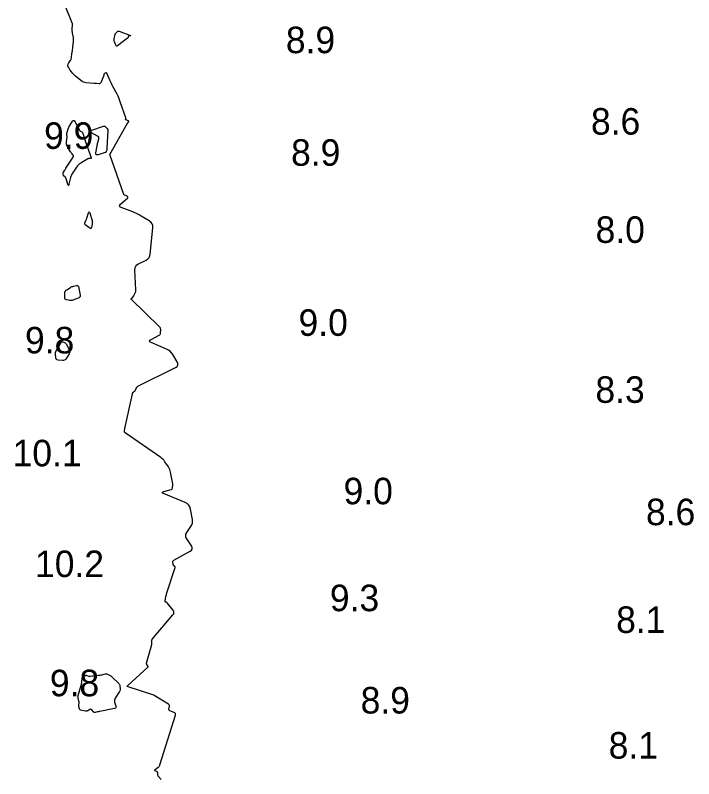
# Model space of a CAD drawing. Extents: x 1023796 to 1112670, y 656573 to 837340.
# Drawn here: x 1100706.3 to 1100834.2, y 688188.2 to 688332.1 of the extents above; entities that cross this region are included whole.
import ezdxf

# ---------------------------------------------------------------- set-up
doc = ezdxf.new("R2010")
doc.units = 0
doc.layers.add('V-CHAN-CONT-10FT', color=7, linetype='Continuous')
doc.layers.add('V-TOPO-SOUN', color=7, linetype='Continuous')

msp = doc.modelspace()

# ---------------------------------------------------------------- linework, layer by layer
at = {"layer": 'V-CHAN-CONT-10FT'}
msp.add_lwpolyline([(1100733.76, 688188.01), (1100733.28, 688188.6), (1100733.24, 688188.67), (1100733.2, 688188.73), (1100733.18, 688188.81), (1100733.17, 688188.88), (1100733.15, 688189.19), (1100733.13, 688189.27), (1100733.11, 688189.33), (1100733.06, 688189.39), (1100733.01, 688189.43), (1100732.67, 688189.65), (1100732.61, 688189.7), (1100732.59, 688189.75), (1100732.61, 688189.81), (1100732.66, 688189.87), (1100733.23, 688190.32), (1100733.34, 688190.42), (1100733.43, 688190.53), (1100733.5, 688190.66), (1100733.55, 688190.8), (1100736.46, 688200.14), (1100736.49, 688200.3), (1100736.46, 688200.44), (1100736.37, 688200.55), (1100736.22, 688200.63), (1100735.44, 688200.93), (1100735.33, 688200.99), (1100735.26, 688201.07), (1100735.23, 688201.17), (1100735.24, 688201.29), (1100735.34, 688201.83), (1100735.34, 688201.96), (1100735.31, 688202.07), (1100735.25, 688202.16), (1100735.15, 688202.24), (1100732.47, 688203.82), (1100732.46, 688203.83), (1100732.45, 688203.84), (1100732.45, 688203.85), (1100732.45, 688203.86), (1100732.44, 688203.91), (1100732.44, 688203.92), (1100732.43, 688203.93), (1100732.42, 688203.94), (1100732.41, 688203.94), (1100727.39, 688205.52), (1100727.37, 688205.53), (1100727.36, 688205.54), (1100727.36, 688205.55), (1100727.37, 688205.57), (1100727.44, 688205.65), (1100727.45, 688205.67), (1100727.47, 688205.68), (1100727.49, 688205.7), (1100727.51, 688205.72), (1100731.25, 688209.16), (1100731.3, 688209.22), (1100731.32, 688209.28), (1100731.31, 688209.34), (1100731.27, 688209.4), (1100731.09, 688209.67), (1100731.05, 688209.74), (1100731.03, 688209.81), (1100731.02, 688209.88), (1100731.04, 688209.96), (1100732.01, 688213.47), (1100732.03, 688213.56), (1100732.05, 688213.65), (1100732.05, 688213.75), (1100732.05, 688213.84), (1100732.04, 688214.22), (1100732.05, 688214.31), (1100732.07, 688214.39), (1100732.11, 688214.47), (1100732.16, 688214.55), (1100735.99, 688219.04), (1100736.14, 688219.27), (1100736.19, 688219.5), (1100736.15, 688219.73), (1100736.01, 688219.97), (1100734.93, 688221.31), (1100734.89, 688221.34), (1100734.86, 688221.37), (1100734.82, 688221.39), (1100734.78, 688221.41), (1100734.6, 688221.47), (1100734.56, 688221.49), (1100734.53, 688221.52), (1100734.52, 688221.55), (1100734.52, 688221.6), (1100734.68, 688222.53), (1100734.72, 688222.69), (1100734.76, 688222.86), (1100734.8, 688223.03), (1100734.85, 688223.19), (1100736.4, 688227.95), (1100736.41, 688228.02), (1100736.41, 688228.08), (1100736.38, 688228.13), (1100736.34, 688228.18), (1100736.13, 688228.37), (1100736.08, 688228.42), (1100736.05, 688228.48), (1100736.03, 688228.54), (1100736.02, 688228.61), (1100735.99, 688229.08), (1100736, 688229.17), (1100736.03, 688229.26), (1100736.09, 688229.32), (1100736.16, 688229.38), (1100739.23, 688231.03), (1100739.5, 688231.23), (1100739.63, 688231.46), (1100739.62, 688231.73), (1100739.48, 688232.04), (1100738.6, 688233.38), (1100738.45, 688233.67), (1100738.41, 688233.97), (1100738.46, 688234.26), (1100738.6, 688234.56), (1100739.39, 688235.73), (1100739.56, 688236.03), (1100739.66, 688236.34), (1100739.69, 688236.67), (1100739.67, 688237.01), (1100739.32, 688238.98), (1100739.2, 688239.39), (1100739, 688239.74), (1100738.71, 688240.01), (1100738.33, 688240.22), (1100734.24, 688241.9), (1100734.04, 688242.01), (1100733.98, 688242.11), (1100734.05, 688242.2), (1100734.26, 688242.28), (1100735.68, 688242.69), (1100735.79, 688242.74), (1100735.87, 688242.81), (1100735.92, 688242.9), (1100735.94, 688243.02), (1100735.97, 688243.53), (1100735.97, 688243.66), (1100735.96, 688243.79), (1100735.95, 688243.92), (1100735.93, 688244.04), (1100735.57, 688245.92), (1100735.5, 688246.19), (1100735.41, 688246.46), (1100735.29, 688246.71), (1100735.14, 688246.96), (1100734.49, 688247.91), (1100734.32, 688248.14), (1100734.13, 688248.35), (1100733.92, 688248.54), (1100733.69, 688248.71), (1100726.98, 688253.37), (1100726.93, 688253.42), (1100726.89, 688253.47), (1100726.87, 688253.53), (1100726.87, 688253.6), (1100726.89, 688253.88), (1100726.9, 688253.95), (1100726.91, 688254.02), (1100726.92, 688254.09), (1100726.93, 688254.15), (1100728.35, 688260.73), (1100728.38, 688260.82), (1100728.41, 688260.9), (1100728.46, 688260.97), (1100728.53, 688261.03), (1100728.8, 688261.28), (1100728.86, 688261.34), (1100728.92, 688261.41), (1100728.97, 688261.49), (1100729.01, 688261.57), (1100729.17, 688261.9), (1100729.21, 688261.98), (1100729.27, 688262.05), (1100729.33, 688262.1), (1100729.41, 688262.15), (1100736.51, 688265.69), (1100736.8, 688265.89), (1100736.95, 688266.14), (1100736.95, 688266.42), (1100736.82, 688266.75), (1100735.98, 688268.14), (1100735.75, 688268.46), (1100735.48, 688268.74), (1100735.17, 688268.97), (1100734.81, 688269.15), (1100731.9, 688270.39), (1100731.67, 688270.52), (1100731.59, 688270.66), (1100731.66, 688270.81), (1100731.88, 688270.96), (1100733.38, 688271.75), (1100733.5, 688271.83), (1100733.59, 688271.93), (1100733.64, 688272.05), (1100733.67, 688272.19), (1100733.69, 688272.79), (1100733.68, 688272.94), (1100733.65, 688273.07), (1100733.58, 688273.2), (1100733.49, 688273.31), (1100728.11, 688278.53), (1100728.09, 688278.56), (1100728.09, 688278.59), (1100728.1, 688278.61), (1100728.12, 688278.64), (1100728.26, 688278.73), (1100728.29, 688278.75), (1100728.33, 688278.78), (1100728.35, 688278.81), (1100728.38, 688278.85), (1100728.6, 688279.2), (1100728.65, 688279.27), (1100728.69, 688279.34), (1100728.73, 688279.41), (1100728.76, 688279.49), (1100728.95, 688279.9), (1100728.99, 688280), (1100729.02, 688280.09), (1100729.03, 688280.19), (1100729.03, 688280.3), (1100728.84, 688284.09), (1100728.87, 688284.46), (1100728.99, 688284.78), (1100729.21, 688285.03), (1100729.52, 688285.23), (1100730.94, 688285.93), (1100731.26, 688286.13), (1100731.5, 688286.39), (1100731.66, 688286.7), (1100731.73, 688287.06), (1100732.21, 688292), (1100732.2, 688292.42), (1100732.08, 688292.78), (1100731.86, 688293.08), (1100731.53, 688293.33), (1100730.01, 688294.22), (1100729.62, 688294.44), (1100729.23, 688294.64), (1100728.83, 688294.82), (1100728.43, 688294.99), (1100726.25, 688295.84), (1100726.02, 688295.97), (1100725.93, 688296.12), (1100725.97, 688296.29), (1100726.14, 688296.49), (1100727.47, 688297.67), (1100727.51, 688297.71), (1100727.52, 688297.75), (1100727.51, 688297.79), (1100727.47, 688297.83), (1100727.29, 688297.99), (1100727.25, 688298.03), (1100727.2, 688298.06), (1100727.15, 688298.08), (1100727.1, 688298.1), (1100726.89, 688298.16), (1100726.84, 688298.18), (1100726.8, 688298.21), (1100726.77, 688298.25), (1100726.74, 688298.3), (1100724.17, 688305.63), (1100724.17, 688305.64), (1100724.17, 688305.65), (1100724.17, 688305.66), (1100724.17, 688305.68), (1100724.19, 688305.73), (1100724.19, 688305.74), (1100724.19, 688305.75), (1100724.18, 688305.76), (1100724.17, 688305.76), (1100724.11, 688305.79), (1100724.1, 688305.79), (1100724.1, 688305.8), (1100724.1, 688305.81), (1100724.1, 688305.82), (1100727.45, 688311.71), (1100727.48, 688311.76), (1100727.5, 688311.8), (1100727.53, 688311.84), (1100727.55, 688311.88), (1100727.66, 688312.04), (1100727.67, 688312.08), (1100727.67, 688312.11), (1100727.65, 688312.13), (1100727.62, 688312.15), (1100727.13, 688312.35), (1100727.1, 688312.37), (1100727.08, 688312.39), (1100727.07, 688312.42), (1100727.08, 688312.45), (1100727.13, 688312.61), (1100727.14, 688312.64), (1100727.14, 688312.68), (1100727.13, 688312.72), (1100727.12, 688312.76), (1100726.08, 688315.78), (1100725.95, 688316.13), (1100725.81, 688316.48), (1100725.65, 688316.83), (1100725.48, 688317.17), (1100724.68, 688318.67), (1100724.55, 688318.92), (1100724.42, 688319.18), (1100724.29, 688319.44), (1100724.17, 688319.7), (1100723.52, 688321.16), (1100723.49, 688321.21), (1100723.45, 688321.23), (1100723.41, 688321.24), (1100723.35, 688321.22), (1100723.09, 688321.07), (1100723.05, 688321.04), (1100723.02, 688321.01), (1100723, 688320.97), (1100722.99, 688320.93), (1100722.96, 688320.75), (1100722.96, 688320.71), (1100722.94, 688320.67), (1100722.93, 688320.62), (1100722.91, 688320.58), (1100722.38, 688319.36), (1100722.32, 688319.27), (1100722.25, 688319.21), (1100722.16, 688319.17), (1100722.06, 688319.16), (1100721.6, 688319.18), (1100721.49, 688319.18), (1100721.37, 688319.19), (1100721.26, 688319.19), (1100721.14, 688319.2), (1100719.64, 688319.35), (1100719.37, 688319.39), (1100719.12, 688319.47), (1100718.87, 688319.59), (1100718.65, 688319.75), (1100717.61, 688320.59), (1100717.48, 688320.7), (1100717.36, 688320.82), (1100717.25, 688320.95), (1100717.14, 688321.08), (1100716.64, 688321.73), (1100716.59, 688321.81), (1100716.53, 688321.89), (1100716.48, 688321.98), (1100716.42, 688322.06), (1100716.2, 688322.45), (1100716.17, 688322.51), (1100716.16, 688322.58), (1100716.16, 688322.64), (1100716.19, 688322.71), (1100716.3, 688322.97), (1100716.34, 688323.04), (1100716.37, 688323.1), (1100716.41, 688323.16), (1100716.45, 688323.22), (1100716.68, 688323.51), (1100716.72, 688323.57), (1100716.76, 688323.65), (1100716.79, 688323.72), (1100716.8, 688323.8), (1100717, 688325.16), (1100717.04, 688325.39), (1100717.07, 688325.62), (1100717.1, 688325.85), (1100717.13, 688326.09), (1100717.26, 688327.08), (1100717.28, 688327.28), (1100717.28, 688327.48), (1100717.26, 688327.67), (1100717.23, 688327.87), (1100717.06, 688328.71), (1100717.04, 688328.88), (1100717.02, 688329.05), (1100717.01, 688329.22), (1100717.02, 688329.39), (1100717.09, 688330.33), (1100717.09, 688330.37), (1100717.09, 688330.41), (1100717.08, 688330.45), (1100717.06, 688330.49), (1100716.99, 688330.64), (1100716.97, 688330.67), (1100716.96, 688330.71), (1100716.94, 688330.75), (1100716.92, 688330.79), (1100715.75, 688333.71)], dxfattribs=at)
for points in [[(1100728.08, 688328.2), (1100728.06, 688328.18), (1100728.01, 688328.17), (1100727.67, 688328.11), (1100727.63, 688328.1), (1100727.61, 688328.08), (1100727.59, 688328.05), (1100727.57, 688328.02), (1100727.53, 688327.87), (1100727.52, 688327.84), (1100727.5, 688327.81), (1100727.48, 688327.78), (1100727.45, 688327.75), (1100725.57, 688326.32), (1100725.45, 688326.25), (1100725.35, 688326.25), (1100725.27, 688326.31), (1100725.21, 688326.43), (1100724.99, 688327.03), (1100724.95, 688327.18), (1100724.93, 688327.33), (1100724.93, 688327.48), (1100724.95, 688327.64), (1100725.14, 688328.48), (1100725.16, 688328.56), (1100725.2, 688328.63), (1100725.25, 688328.7), (1100725.31, 688328.76), (1100725.57, 688328.99), (1100725.64, 688329.04), (1100725.71, 688329.06), (1100725.79, 688329.06), (1100725.87, 688329.04), (1100728.01, 688328.24), (1100728.06, 688328.22)], [(1100715.94, 688307.76), (1100715.92, 688307.95), (1100715.92, 688308.14), (1100716.03, 688309.24), (1100716.03, 688309.29), (1100716.03, 688309.34), (1100716.03, 688309.39), (1100716.02, 688309.43), (1100715.98, 688309.62), (1100715.97, 688309.67), (1100715.97, 688309.72), (1100715.98, 688309.76), (1100715.99, 688309.81), (1100716.27, 688310.69), (1100716.33, 688310.85), (1100716.39, 688311), (1100716.47, 688311.15), (1100716.56, 688311.3), (1100717.07, 688312.08), (1100717.18, 688312.22), (1100717.29, 688312.26), (1100717.4, 688312.21), (1100717.5, 688312.07), (1100718.39, 688310.4), (1100718.42, 688310.34), (1100718.47, 688310.29), (1100718.52, 688310.24), (1100718.58, 688310.21), (1100718.84, 688310.07), (1100718.9, 688310.03), (1100718.94, 688309.98), (1100718.98, 688309.93), (1100719.01, 688309.86), (1100719.53, 688308.19), (1100719.63, 688307.89), (1100719.73, 688307.59), (1100719.83, 688307.3), (1100719.94, 688307), (1100720.61, 688305.19), (1100720.62, 688305.13), (1100720.61, 688305.09), (1100720.57, 688305.07), (1100720.51, 688305.06), (1100720.24, 688305.06), (1100720.17, 688305.05), (1100720.1, 688305.04), (1100720.04, 688305.02), (1100719.98, 688304.99), (1100718.63, 688304.22), (1100718.4, 688304.07), (1100718.19, 688303.89), (1100718, 688303.69), (1100717.84, 688303.46), (1100716.97, 688302.12), (1100716.85, 688301.91), (1100716.75, 688301.69), (1100716.67, 688301.47), (1100716.61, 688301.23), (1100716.4, 688300.24), (1100716.36, 688300.07), (1100716.3, 688300.01), (1100716.24, 688300.06), (1100716.17, 688300.23), (1100715.79, 688301.44), (1100715.77, 688301.49), (1100715.74, 688301.53), (1100715.71, 688301.57), (1100715.66, 688301.6), (1100715.48, 688301.71), (1100715.44, 688301.74), (1100715.4, 688301.77), (1100715.38, 688301.81), (1100715.37, 688301.86), (1100715.3, 688302.19), (1100715.3, 688302.27), (1100715.3, 688302.33), (1100715.32, 688302.4), (1100715.35, 688302.47), (1100715.61, 688302.89), (1100715.67, 688302.98), (1100715.73, 688303.07), (1100715.79, 688303.16), (1100715.84, 688303.25), (1100717.2, 688305.34), (1100717.24, 688305.43), (1100717.25, 688305.51), (1100717.23, 688305.6), (1100717.18, 688305.68), (1100716.92, 688306), (1100716.86, 688306.09), (1100716.8, 688306.17), (1100716.75, 688306.26), (1100716.69, 688306.34), (1100716.08, 688307.4), (1100716, 688307.57)], [(1100723.69, 688310.62), (1100723.71, 688310.53), (1100723.72, 688310.43), (1100723.56, 688306.96), (1100723.55, 688306.89), (1100723.54, 688306.81), (1100723.53, 688306.74), (1100723.51, 688306.67), (1100723.43, 688306.38), (1100723.41, 688306.31), (1100723.37, 688306.26), (1100723.32, 688306.21), (1100723.25, 688306.19), (1100721.88, 688305.77), (1100721.66, 688305.73), (1100721.52, 688305.78), (1100721.45, 688305.92), (1100721.46, 688306.14), (1100721.7, 688307.43), (1100721.73, 688307.6), (1100721.77, 688307.77), (1100721.81, 688307.94), (1100721.85, 688308.11), (1100722.03, 688308.77), (1100722.05, 688308.93), (1100722.02, 688309.06), (1100721.94, 688309.18), (1100721.81, 688309.27), (1100720.64, 688309.93), (1100720.46, 688310.07), (1100720.41, 688310.19), (1100720.48, 688310.3), (1100720.68, 688310.39), (1100722.89, 688311.15), (1100722.99, 688311.17), (1100723.09, 688311.17), (1100723.17, 688311.14), (1100723.25, 688311.08), (1100723.57, 688310.79), (1100723.64, 688310.71)], [(1100720.54, 688291.84), (1100720.44, 688291.85), (1100720.33, 688291.92), (1100719.48, 688292.59), (1100719.4, 688292.66), (1100719.37, 688292.75), (1100719.36, 688292.84), (1100719.39, 688292.94), (1100719.59, 688293.36), (1100719.64, 688293.47), (1100719.68, 688293.58), (1100719.72, 688293.69), (1100719.76, 688293.8), (1100720.08, 688294.8), (1100720.14, 688294.96), (1100720.21, 688295.01), (1100720.27, 688294.96), (1100720.33, 688294.8), (1100720.75, 688293.34), (1100720.79, 688293.18), (1100720.81, 688293.02), (1100720.8, 688292.86), (1100720.78, 688292.69), (1100720.65, 688292.04), (1100720.61, 688291.91)], [(1100718.43, 688278.96), (1100718.31, 688278.83), (1100718.13, 688278.73), (1100717.14, 688278.38), (1100717, 688278.33), (1100716.85, 688278.31), (1100716.69, 688278.31), (1100716.54, 688278.33), (1100715.93, 688278.45), (1100715.79, 688278.5), (1100715.7, 688278.57), (1100715.64, 688278.68), (1100715.62, 688278.83), (1100715.63, 688279.75), (1100715.65, 688279.93), (1100715.72, 688280.09), (1100715.82, 688280.22), (1100715.97, 688280.34), (1100716.7, 688280.77), (1100716.83, 688280.85), (1100716.97, 688280.91), (1100717.11, 688280.96), (1100717.26, 688281), (1100717.85, 688281.14), (1100717.98, 688281.15), (1100718.08, 688281.11), (1100718.15, 688281.03), (1100718.2, 688280.91), (1100718.48, 688279.33), (1100718.48, 688279.13)], [(1100715.08, 688270.5), (1100715.15, 688270.51), (1100715.23, 688270.5), (1100715.58, 688270.37), (1100715.66, 688270.34), (1100715.74, 688270.29), (1100715.8, 688270.22), (1100715.85, 688270.15), (1100716.46, 688269.05), (1100716.55, 688268.84), (1100716.57, 688268.63), (1100716.53, 688268.43), (1100716.43, 688268.22), (1100715.79, 688267.26), (1100715.67, 688267.12), (1100715.52, 688267.03), (1100715.36, 688266.98), (1100715.17, 688266.98), (1100714.35, 688267.07), (1100714.19, 688267.12), (1100714.07, 688267.2), (1100713.99, 688267.31), (1100713.95, 688267.47), (1100713.87, 688268.18), (1100713.87, 688268.36), (1100713.89, 688268.53), (1100713.94, 688268.69), (1100714.02, 688268.85), (1100714.96, 688270.4), (1100715.02, 688270.47)], [(1100724.38, 688207.46), (1100724.47, 688207.38), (1100724.56, 688207.3), (1100725.79, 688206.1), (1100725.88, 688206.01), (1100725.94, 688205.9), (1100725.99, 688205.78), (1100726.01, 688205.65), (1100726.06, 688205.12), (1100726.06, 688204.99), (1100726.04, 688204.86), (1100726, 688204.74), (1100725.94, 688204.62), (1100725.11, 688203.33), (1100725.02, 688203.16), (1100724.98, 688202.98), (1100724.97, 688202.8), (1100725.01, 688202.61), (1100725.25, 688201.86), (1100725.28, 688201.69), (1100725.25, 688201.56), (1100725.15, 688201.46), (1100724.99, 688201.4), (1100722.19, 688200.84), (1100722.08, 688200.81), (1100721.98, 688200.79), (1100721.87, 688200.77), (1100721.77, 688200.74), (1100721.34, 688200.64), (1100721.24, 688200.63), (1100721.15, 688200.64), (1100721.07, 688200.69), (1100721, 688200.76), (1100720.68, 688201.15), (1100720.61, 688201.22), (1100720.53, 688201.26), (1100720.44, 688201.25), (1100720.34, 688201.21), (1100719.95, 688200.98), (1100719.85, 688200.93), (1100719.75, 688200.91), (1100719.65, 688200.9), (1100719.54, 688200.91), (1100718.59, 688201.1), (1100718.51, 688201.13), (1100718.44, 688201.18), (1100718.39, 688201.25), (1100718.36, 688201.34), (1100718.27, 688201.75), (1100718.25, 688201.84), (1100718.25, 688201.92), (1100718.25, 688202.01), (1100718.26, 688202.09), (1100718.31, 688202.43), (1100718.32, 688202.52), (1100718.32, 688202.6), (1100718.31, 688202.69), (1100718.29, 688202.77), (1100718.13, 688203.33), (1100718.11, 688203.46), (1100718.1, 688203.58), (1100718.11, 688203.7), (1100718.13, 688203.82), (1100718.74, 688205.97), (1100718.77, 688206.09), (1100718.8, 688206.23), (1100718.82, 688206.36), (1100718.83, 688206.49), (1100718.86, 688207.08), (1100718.88, 688207.18), (1100718.92, 688207.26), (1100718.98, 688207.33), (1100719.06, 688207.39), (1100719.48, 688207.61), (1100719.55, 688207.64), (1100719.63, 688207.65), (1100719.7, 688207.65), (1100719.77, 688207.62), (1100720.07, 688207.5), (1100720.14, 688207.47), (1100720.22, 688207.46), (1100720.29, 688207.45), (1100720.37, 688207.46), (1100721.97, 688207.67), (1100722.13, 688207.69), (1100722.29, 688207.71), (1100722.44, 688207.74), (1100722.6, 688207.77), (1100723.31, 688207.9), (1100723.43, 688207.91), (1100723.54, 688207.9), (1100723.65, 688207.87), (1100723.76, 688207.82), (1100724.18, 688207.59), (1100724.28, 688207.53)]]:
    msp.add_lwpolyline(points, close=True, dxfattribs=at)

# ---------------------------------------------------------------- texts
at = {"layer": 'V-TOPO-SOUN'}
for s, p in [('8.9', (1100757.29, 688324.92)), ('8.6', (1100814.81, 688309.57)), ('9.9', (1100711.71, 688306.88)), ('8.9', (1100758.27, 688303.7)), ('8.0', (1100815.68, 688289.16)), ('9.0', (1100759.68, 688271.64)), ('9.8', (1100708.11, 688268.33)), ('8.3', (1100815.65, 688259.01)), ('10.1 ', (1100705.77, 688247.04)), ('9.0', (1100768.17, 688239.89)), ('8.6', (1100825.18, 688235.95)), ('10.2 ', (1100710, 688226.17)), ('9.3', (1100765.59, 688219.74)), ('8.1', (1100819.56, 688215.64)), ('9.8', (1100712.8, 688203.7)), ('8.9', (1100771.39, 688200.45)), ('8.1', (1100818.15, 688191.95))]:
    msp.add_text(s, height=5, dxfattribs=at).set_placement(p)

doc.saveas('drawing.dxf')
